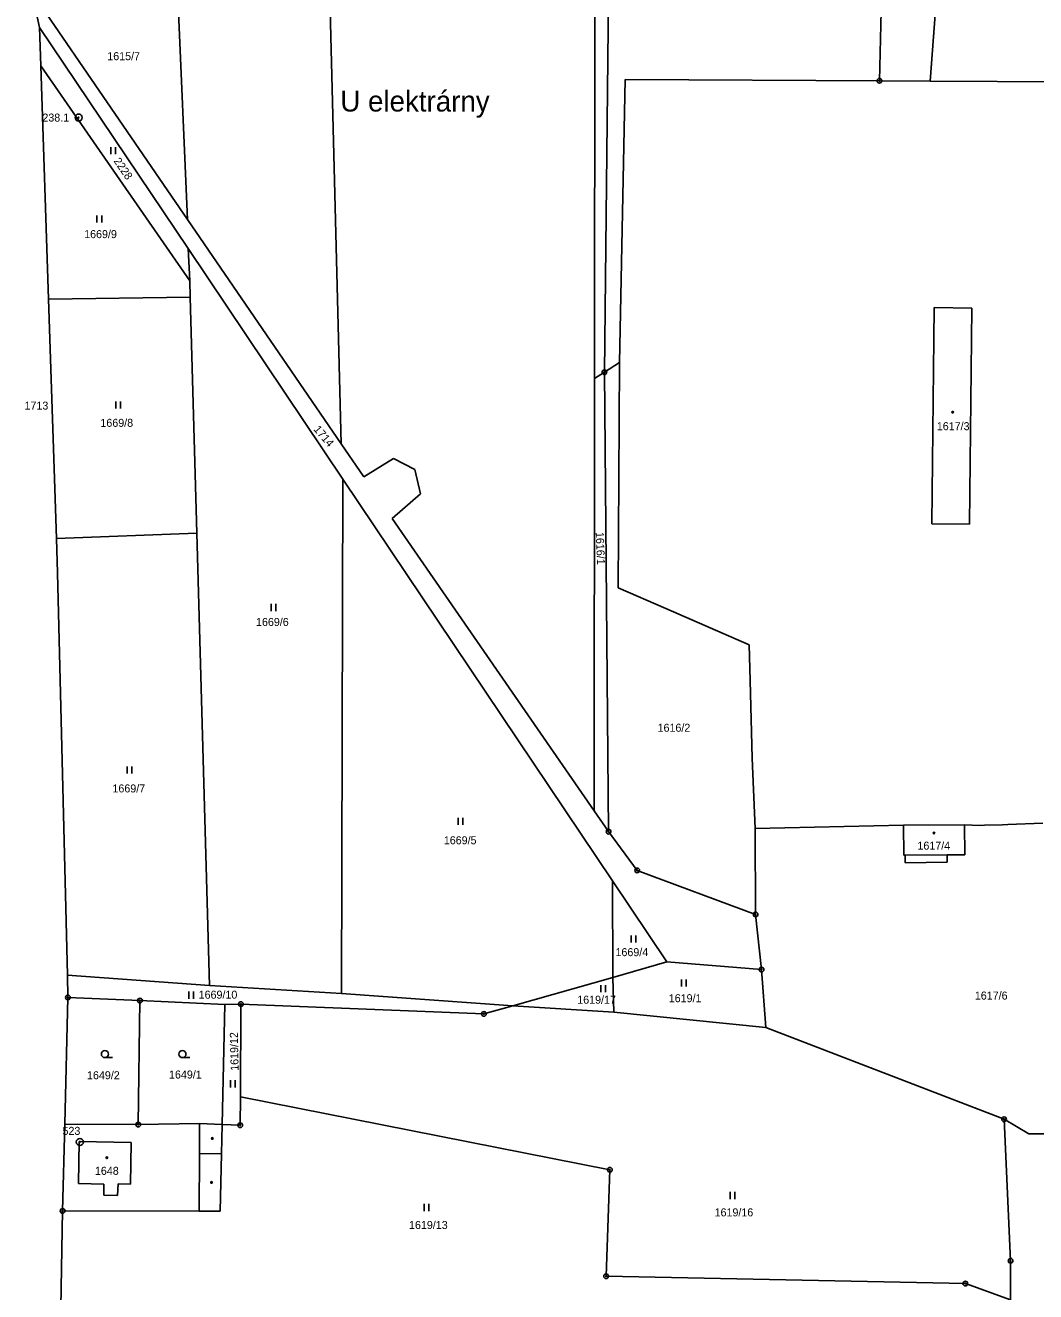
# Model space of a CAD drawing. Extents: x -763296 to -761805, y -1153670 to -1152034.
# Drawn here: x -762755.5 to -762540.8, y -1152808 to -1152539 of the extents above; entities that cross this region are included whole.
import ezdxf

# ---------------------------------------------------------------- set-up
doc = ezdxf.new("R2010")
doc.units = 0
for name, color, linetype in [('Vrstva 1', 7, 'Continuous'), ('Vrstva 15', 7, 'Continuous'), ('Vrstva 17', 7, 'Continuous'), ('Vrstva 18', 7, 'Continuous'), ('Vrstva 19', 7, 'Continuous'), ('Vrstva 24', 7, 'Continuous'), ('Vrstva 25', 7, 'Continuous'), ('Vrstva 4', 7, 'Continuous'), ('Vrstva 6', 7, 'Continuous')]:
    doc.layers.add(name, color=color, linetype=linetype)

msp = doc.modelspace()

# ---------------------------------------------------------------- linework, layer by layer
at = {"layer": 'Vrstva 1'}
for p, q in [((-762572.52, -1152489.33), (-762574.04, -1152550.81)), ((-762563.28, -1152550.87), (-762558.66, -1152489.1)), ((-762634.44, -1152490.71), (-762634.54, -1152614.04)), ((-762754.04, -1152532.11), (-762752.45, -1152539.49)), ((-762721.02, -1152580.29), (-762754.04, -1152532.11)), ((-762752.18, -1152547.64), (-762752.45, -1152539.49)), ((-762752.45, -1152539.49), (-762720.91, -1152586.44)), ((-762750.53, -1152597.15), (-762752.18, -1152547.64)), ((-762628.06, -1152550.51), (-762629.22, -1152610.67)), ((-762574.04, -1152550.81), (-762628.06, -1152550.51)), ((-762574.04, -1152550.81), (-762563.28, -1152550.87)), ((-762563.28, -1152550.87), (-762534.53, -1152551.03)), ((-762688.39, -1152627.94), (-762721.02, -1152580.29)), ((-762720.91, -1152586.44), (-762687.99, -1152635.4)), ((-762748.84, -1152648.01), (-762750.53, -1152597.15)), ((-762562.46, -1152605.66), (-762562.38, -1152598.99)), ((-762562.38, -1152598.99), (-762554.38, -1152599.09)), ((-762554.38, -1152599.09), (-762554.46, -1152605.75)), ((-762562.53, -1152612.17), (-762562.46, -1152605.66)), ((-762554.46, -1152605.75), (-762554.53, -1152612.26)), ((-762632.44, -1152612.71), (-762634.54, -1152614.04)), ((-762629.22, -1152610.67), (-762632.44, -1152612.71)), ((-762632.44, -1152612.71), (-762631.58, -1152710.27)), ((-762629.22, -1152610.67), (-762629.38, -1152635.24)), ((-762562.61, -1152618.69), (-762562.53, -1152612.17)), ((-762554.53, -1152612.26), (-762554.6, -1152618.78)), ((-762634.54, -1152614.04), (-762634.62, -1152705.87)), ((-762562.68, -1152625.2), (-762562.61, -1152618.69)), ((-762554.6, -1152618.78), (-762554.67, -1152625.29)), ((-762562.75, -1152631.71), (-762562.68, -1152625.2)), ((-762554.67, -1152625.29), (-762554.75, -1152631.8)), ((-762683.57, -1152634.92), (-762688.39, -1152627.94)), ((-762677.26, -1152630.99), (-762683.57, -1152634.92)), ((-762672.7, -1152633.39), (-762677.26, -1152630.99)), ((-762562.82, -1152638.23), (-762562.75, -1152631.71)), ((-762554.75, -1152631.8), (-762554.82, -1152638.32)), ((-762671.55, -1152638.55), (-762672.7, -1152633.39)), ((-762687.99, -1152635.4), (-762630.73, -1152720.72)), ((-762629.38, -1152635.24), (-762629.53, -1152658.49)), ((-762677.52, -1152643.77), (-762671.55, -1152638.55)), ((-762562.9, -1152644.89), (-762562.82, -1152638.23)), ((-762554.82, -1152638.32), (-762554.89, -1152644.98)), ((-762634.62, -1152705.87), (-762677.52, -1152643.77)), ((-762554.89, -1152644.98), (-762562.9, -1152644.89)), ((-762748.6, -1152655.27), (-762748.84, -1152648.01)), ((-762746.52, -1152740.77), (-762748.6, -1152655.27)), ((-762629.53, -1152658.49), (-762619.42, -1152662.89)), ((-762619.42, -1152662.89), (-762601.73, -1152670.58)), ((-762601.48, -1152678.17), (-762601.73, -1152670.58)), ((-762601.09, -1152694.66), (-762601.48, -1152678.17)), ((-762600.43, -1152709.59), (-762601.09, -1152694.66)), ((-762631.58, -1152710.27), (-762634.62, -1152705.87)), ((-762568.91, -1152708.87), (-762600.43, -1152709.59)), ((-762600.34, -1152727.84), (-762600.43, -1152709.59)), ((-762555.96, -1152708.83), (-762568.91, -1152708.87)), ((-762568.84, -1152715.29), (-762568.91, -1152708.87)), ((-762552.71, -1152708.95), (-762555.96, -1152708.83)), ((-762555.96, -1152708.83), (-762555.89, -1152715.16)), ((-762551.72, -1152708.92), (-762552.71, -1152708.95)), ((-762547.86, -1152708.81), (-762551.72, -1152708.92)), ((-762546.77, -1152708.77), (-762547.86, -1152708.81)), ((-762539.34, -1152708.5), (-762546.77, -1152708.77)), ((-762631.58, -1152710.27), (-762625.48, -1152718.5)), ((-762568.55, -1152715.29), (-762568.84, -1152715.29)), ((-762568.54, -1152716.86), (-762568.55, -1152715.29)), ((-762555.89, -1152715.16), (-762559.65, -1152715.2)), ((-762559.65, -1152715.2), (-762559.63, -1152716.77)), ((-762559.63, -1152716.77), (-762568.54, -1152716.86)), ((-762630.73, -1152720.72), (-762619.16, -1152737.94)), ((-762625.48, -1152718.5), (-762600.34, -1152727.84)), ((-762599.07, -1152739.56), (-762600.34, -1152727.84)), ((-762630.67, -1152741.21), (-762619.16, -1152737.94)), ((-762599.07, -1152739.56), (-762619.16, -1152737.94)), ((-762598.17, -1152751.85), (-762599.07, -1152739.56)), ((-762746.43, -1152745.48), (-762746.52, -1152740.77)), ((-762651.91, -1152747.23), (-762630.67, -1152741.21)), ((-762746.43, -1152745.48), (-762747.09, -1152772.41)), ((-762731.11, -1152746.14), (-762746.43, -1152745.48)), ((-762731.47, -1152772.48), (-762731.11, -1152746.14)), ((-762731.11, -1152746.14), (-762713.08, -1152746.95)), ((-762713.08, -1152746.95), (-762713.63, -1152772.45)), ((-762713.08, -1152746.95), (-762709.66, -1152746.9)), ((-762709.66, -1152746.9), (-762709.78, -1152766.59)), ((-762658.05, -1152748.97), (-762709.66, -1152746.9)), ((-762658.05, -1152748.97), (-762651.91, -1152747.23)), ((-762547.55, -1152771.36), (-762598.17, -1152751.85)), ((-762709.78, -1152766.59), (-762709.82, -1152772.63)), ((-762709.78, -1152766.59), (-762631.29, -1152782.08)), ((-762547.55, -1152771.36), (-762546.17, -1152801.38)), ((-762542.3, -1152774.42), (-762547.55, -1152771.36)), ((-762747.09, -1152772.41), (-762747.54, -1152790.8)), ((-762747.09, -1152772.41), (-762731.47, -1152772.48)), ((-762718.46, -1152772.22), (-762731.47, -1152772.48)), ((-762713.63, -1152772.45), (-762718.46, -1152772.22)), ((-762713.63, -1152772.45), (-762713.78, -1152778.69)), ((-762709.82, -1152772.63), (-762713.63, -1152772.45)), ((-762532.99, -1152774.42), (-762542.3, -1152774.42)), ((-762713.78, -1152778.69), (-762714.06, -1152790.88)), ((-762632.09, -1152804.67), (-762631.29, -1152782.08)), ((-762747.54, -1152790.8), (-762747.92, -1152811.23)), ((-762747.54, -1152790.8), (-762718.52, -1152790.9)), ((-762714.06, -1152790.88), (-762718.52, -1152790.9)), ((-762546.17, -1152801.38), (-762546.17, -1152809.66)), ((-762555.78, -1152806.25), (-762632.09, -1152804.67)), ((-762546.17, -1152809.66), (-762555.78, -1152806.25))]:
    msp.add_line(p, q, dxfattribs=at)
at = {"layer": 'Vrstva 24'}
for centre, radius in [((-762574.04, -1152550.81), 0.5), ((-762574.04, -1152550.81), 0.1), ((-762744.14, -1152558.62), 0.75), ((-762744.14, -1152558.62), 0.1), ((-762632.44, -1152612.71), 0.5), ((-762632.44, -1152612.71), 0.1), ((-762631.58, -1152710.27), 0.5), ((-762631.58, -1152710.27), 0.1), ((-762625.48, -1152718.5), 0.5), ((-762625.48, -1152718.5), 0.1), ((-762600.34, -1152727.84), 0.5), ((-762600.34, -1152727.84), 0.1), ((-762599.07, -1152739.56), 0.5), ((-762599.07, -1152739.56), 0.1), ((-762746.43, -1152745.48), 0.5), ((-762746.43, -1152745.48), 0.1), ((-762731.11, -1152746.14), 0.5), ((-762731.11, -1152746.14), 0.1), ((-762709.66, -1152746.9), 0.5), ((-762709.66, -1152746.9), 0.1), ((-762658.05, -1152748.97), 0.5), ((-762658.05, -1152748.97), 0.1), ((-762547.55, -1152771.36), 0.5), ((-762547.55, -1152771.36), 0.1), ((-762731.47, -1152772.48), 0.5), ((-762731.47, -1152772.48), 0.1), ((-762709.82, -1152772.63), 0.5), ((-762709.82, -1152772.63), 0.1), ((-762743.89, -1152776.17), 0.75), ((-762743.89, -1152776.17), 0.1), ((-762631.29, -1152782.08), 0.5), ((-762631.29, -1152782.08), 0.1), ((-762747.54, -1152790.8), 0.5), ((-762747.54, -1152790.8), 0.1), ((-762546.17, -1152801.38), 0.5), ((-762546.17, -1152801.38), 0.1), ((-762632.09, -1152804.67), 0.5), ((-762632.09, -1152804.67), 0.1), ((-762555.78, -1152806.25), 0.5), ((-762555.78, -1152806.25), 0.1)]:
    msp.add_circle(centre, radius, dxfattribs=at)
at = {"layer": 'Vrstva 25'}
for p, q in [((-762737.34, -1152566.4), (-762737.34, -1152564.9)), ((-762736.34, -1152566.4), (-762736.34, -1152564.9)), ((-762740.25, -1152580.93), (-762740.25, -1152579.43)), ((-762739.25, -1152580.93), (-762739.25, -1152579.43)), ((-762736.25, -1152620.42), (-762736.25, -1152618.92)), ((-762735.25, -1152620.42), (-762735.25, -1152618.92)), ((-762703.23, -1152663.42), (-762703.23, -1152661.92)), ((-762702.23, -1152663.42), (-762702.23, -1152661.92)), ((-762733.86, -1152697.93), (-762733.86, -1152696.43)), ((-762732.86, -1152697.93), (-762732.86, -1152696.43)), ((-762663.52, -1152708.85), (-762663.52, -1152707.35)), ((-762662.52, -1152708.85), (-762662.52, -1152707.35)), ((-762626.79, -1152733.84), (-762626.79, -1152732.34)), ((-762625.79, -1152733.84), (-762625.79, -1152732.34)), ((-762616.11, -1152743.17), (-762616.11, -1152741.67)), ((-762615.11, -1152743.17), (-762615.11, -1152741.67)), ((-762720.71, -1152745.74), (-762720.71, -1152744.24)), ((-762719.71, -1152745.74), (-762719.71, -1152744.24)), ((-762633.24, -1152744.35), (-762633.24, -1152742.85)), ((-762632.24, -1152744.35), (-762632.24, -1152742.85)), ((-762738.57, -1152758.26), (-762736.97, -1152758.26)), ((-762722.09, -1152758.26), (-762720.49, -1152758.26)), ((-762711.89, -1152764.57), (-762711.89, -1152763.07)), ((-762710.89, -1152764.57), (-762710.89, -1152763.07)), ((-762605.73, -1152788.29), (-762605.73, -1152786.79)), ((-762604.73, -1152788.29), (-762604.73, -1152786.79)), ((-762670.76, -1152790.84), (-762670.76, -1152789.34)), ((-762669.76, -1152790.84), (-762669.76, -1152789.34))]:
    msp.add_line(p, q, dxfattribs=at)
msp.add_lwpolyline([(-762558.4, -1152621.05), (-762558.31, -1152621.2), (-762558.4, -1152621.35), (-762558.58, -1152621.35), (-762558.67, -1152621.2), (-762558.58, -1152621.05)], close=True, dxfattribs=at)
for centre, radius in [((-762562.43, -1152710.57), 0.175), ((-762738.57, -1152757.51), 0.75), ((-762722.09, -1152757.51), 0.75), ((-762715.74, -1152775.43), 0.175), ((-762738.14, -1152779.52), 0.175), ((-762715.92, -1152784.76), 0.175)]:
    msp.add_circle(centre, radius, dxfattribs=at)
at = {"layer": 'Vrstva 4'}
for p, q in [((-762568.55, -1152715.29), (-762559.65, -1152715.2)), ((-762718.46, -1152772.22), (-762718.5, -1152778.63)), ((-762744.14, -1152784.98), (-762744.04, -1152776.09)), ((-762744.04, -1152776.09), (-762733.02, -1152776.26)), ((-762733.02, -1152776.26), (-762733.16, -1152785.13)), ((-762718.5, -1152778.63), (-762718.52, -1152790.9)), ((-762713.78, -1152778.69), (-762718.5, -1152778.63)), ((-762738.8, -1152785.14), (-762744.14, -1152784.98)), ((-762738.81, -1152787.46), (-762738.8, -1152785.14)), ((-762735.72, -1152785.09), (-762735.9, -1152787.51)), ((-762733.16, -1152785.13), (-762735.72, -1152785.09)), ((-762735.9, -1152787.51), (-762738.81, -1152787.46))]:
    msp.add_line(p, q, dxfattribs=at)
at = {"layer": 'Vrstva 6'}
for p, q in [((-762632.44, -1152612.71), (-762630.45, -1152422.76)), ((-762690.96, -1152527.16), (-762688.39, -1152627.94)), ((-762723.25, -1152529.67), (-762721.02, -1152580.29)), ((-762720.54, -1152593.28), (-762752.18, -1152547.64)), ((-762720.54, -1152593.28), (-762720.91, -1152586.44)), ((-762720.46, -1152596.78), (-762720.54, -1152593.28)), ((-762720.46, -1152596.78), (-762750.53, -1152597.15)), ((-762719.04, -1152646.86), (-762720.46, -1152596.78)), ((-762687.99, -1152635.4), (-762688.32, -1152744.61)), ((-762748.84, -1152648.01), (-762719.04, -1152646.86)), ((-762719.04, -1152646.86), (-762716.36, -1152742.94)), ((-762630.73, -1152720.72), (-762630.67, -1152741.21)), ((-762716.36, -1152742.94), (-762746.52, -1152740.77)), ((-762630.67, -1152741.21), (-762630.46, -1152748.57)), ((-762688.32, -1152744.61), (-762716.36, -1152742.94)), ((-762651.91, -1152747.23), (-762688.32, -1152744.61)), ((-762630.46, -1152748.57), (-762651.91, -1152747.23)), ((-762598.17, -1152751.85), (-762630.46, -1152748.57))]:
    msp.add_line(p, q, dxfattribs=at)

# ---------------------------------------------------------------- texts
at = {"layer": 'Vrstva 15'}
msp.add_text('U elektrárny', height=4.4, dxfattribs=at).set_placement((-762688.553, -1152557.34))
at = {"layer": 'Vrstva 17'}
for s, p in [('238.1', (-762751.848, -1152559.47)), ('523', (-762747.574, -1152774.66))]:
    msp.add_text(s, height=1.7, dxfattribs=at).set_placement(p)
at = {"layer": 'Vrstva 18'}
for s, p in [('1615/7', (-762738.063, -1152546.43)), ('1669/9', (-762742.974, -1152584.22)), ('1713', (-762755.644, -1152620.64)), ('1669/8', (-762739.524, -1152624.3)), ('1669/6', (-762706.464, -1152666.59)), ('1616/2', (-762621.16, -1152689.05)), ('1669/7', (-762736.964, -1152701.94)), ('1669/5', (-762666.571, -1152712.95)), ('1669/4', (-762630.104, -1152736.71)), ('1669/10', (-762718.652, -1152745.74)), ('1619/17', (-762638.227, -1152746.81)), ('1619/1', (-762618.788, -1152746.49)), ('1617/6', (-762553.766, -1152745.93)), ('1649/2', (-762742.368, -1152762.85)), ('1649/1', (-762724.946, -1152762.7)), ('1619/16', (-762609.048, -1152791.97)), ('1619/13', (-762673.965, -1152794.65))]:
    msp.add_text(s, height=1.7, dxfattribs=at).set_placement(p)
for s, rotation, p in [('2228', 304.24059, (-762736.793, -1152567.835)), ('1714', 310.65772, (-762694.343, -1152624.893)), ('1616/1', 272.49873, (-762634.304, -1152646.655)), ('1619/12', 91.21488, (-762710.159, -1152761.04))]:
    msp.add_text(s, height=1.7, rotation=rotation, dxfattribs=at).set_placement(p)
at = {"layer": 'Vrstva 19'}
for s, p in [('1617/3', (-762561.843, -1152625.01)), ('1617/4', (-762565.956, -1152714.09)), ('1648', (-762740.686, -1152783.15))]:
    msp.add_text(s, height=1.7, dxfattribs=at).set_placement(p)

doc.saveas('drawing.dxf')
